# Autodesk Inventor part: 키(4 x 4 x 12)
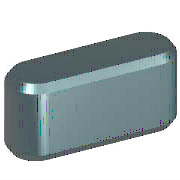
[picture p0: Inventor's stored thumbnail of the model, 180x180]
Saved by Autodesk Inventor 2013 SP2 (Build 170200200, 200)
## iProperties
IsCustomPart: 0
Created: 2009-02
Part Number: 키(4 x 4 x 12)
Material: 강, 연강
Description: 키 및 해당 키홈
Document SubType Name: Modeling
Standard: KS B 1311
Designer: KYOUNG IL JANG
Standards Organization: KS
Language: ko-KR
Size Designation: 4 x 4 x 12
Categories: <MemberInstance><Categories><Category DisplayName="샤프트 부품" InternalName="7f7aeb1f-a693-4053-b835-cee3144e0d98" Mnemonic="SHFT"><Category DisplayName="키" Interna
Density: 7.86 g/cm^3
Mass: 1.38739 g
Surface Area: 1.94869 cm^2
Volume: 0.176513 cm^3
Author: KYOUNG IL JANG
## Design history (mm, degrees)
workplane "Work Plane1"
workplane "Work Plane2"
sketch "스케치1"
  geometry: L1 (2, 2)-(10, 2); L2 (10, -2)-(2, -2); L3 (0, 9.4)-(0, -7.4) reference; L4 (-5, 0)-(30, 0) reference; L5 (12, 0)-(12, 7); A1 r 2 centre (2, 0) between (2, 2) and (2, -2); A2 r 2 centre (10, 0) between (10, -2) and (10, 2)
  constraints: 6 end point, 5 point on circle, 4 tangent, 3 point on line, 2 centre point, 1 horizontal, 1 parallel, 1 perpendicular
  dimensions: "d0" = 2 radius of A1 (= 0.5 x PB); "d13" = 2 radius of A2 (= 0.5 x PB); "d14" = 12 distance between parallel lines of L5 L3 (= NLG)
extrude "본체1" new body sketch "스케치1" taper "d3" = 0 deg; stored distance "d4" = 10
workplane "Work Plane3"
body "Solid1"
chamfer "모따기1" distance "d8" = 0.25 (= PHH); stored, may be unused: second distance "d9" = 0.25 (= PHH), angle "d15" = 45 deg
other parameters: "d1" = -2.5 (= -PNT), "d2" = 1.5 (= PH - PNT), "NLG" = 12 [user parameter; used in 3 equation terms], "PB" = 4 [user parameter; used in 2 equation terms], "PNT" = 2.5 [user parameter; used in 2 equation terms], "PH" = 4 [user parameter; used in 1 equation term], "PHH" = 0.25 [user parameter; used in 2 equation terms], "d10" = 0, "d16" = 0, "d17" = 0, "d18" = 0, "PLB2" = 12 (= NLG) [user parameter], "WDMAX" = 12 [user parameter], "PLB1" = 12 (= NLG) [user parameter], "RR" = 0.08 [user parameter], "PUEB" = 1.8 [user parameter]
